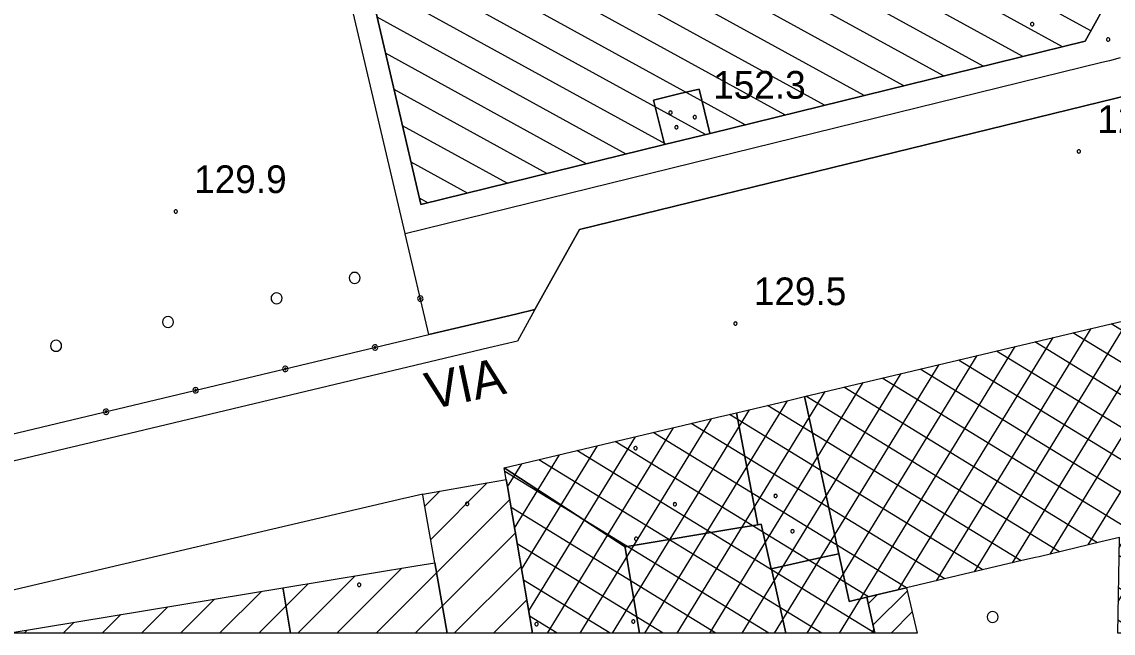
# Model space of a CAD drawing. Extents: x 513373 to 514978, y 5038576 to 5040180.
# Drawn here: x 513585.9 to 513645.1, y 5038580.1 to 5038613.3 of the extents above; entities that cross this region are included whole.
import ezdxf

# ---------------------------------------------------------------- set-up
doc = ezdxf.new("R2010")
doc.units = 0
for name, color, linetype in [('2010300', 7, 'Continuous'), ('B1211', 7, 'Continuous'), ('C1131', 7, 'Continuous'), ('C12211', 7, 'Continuous'), ('C1228', 7, 'Continuous'), ('C21195', 7, 'Continuous'), ('C2911', 7, 'Continuous'), ('CAMP_C12211', 7, 'Continuous'), ('CAMP_C1228', 7, 'Continuous'), ('CAMP_C21195', 7, 'Continuous'), ('Default', 7, 'Continuous'), ('F12107', 7, 'Continuous'), ('F12131', 7, 'Continuous'), ('F12132', 7, 'Continuous'), ('G4315', 7, 'Continuous'), ('TOP500', 7, 'Continuous'), ('TOP920', 7, 'Continuous')]:
    doc.layers.add(name, color=color, linetype=linetype)

# ---------------------------------------------------------------- blocks, each defined once
blk = doc.blocks.new('CAMP_E0F7581C')
at = {"layer": 'CAMP_C12211'}
for p, q in [((6.821, 3.003), (9.881, 6.062)), ((6.501, 4.804), (7.317, 5.62)), ((3.855, -2.085), (11.101, 5.161)), ((5.976, -2.085), (11.411, 3.35)), ((1.734, -2.085), (5.253, 1.434)), ((8.097, -2.085), (11.72, 1.538)), ((-2.509, -2.085), (0.173, 0.597)), ((-0.388, -2.085), (2.713, 1.016)), ((-4.63, -2.085), (-2.367, 0.178)), ((-6.752, -2.085), (-4.907, -0.24)), ((10.219, -2.085), (12.03, -0.273)), ((-10.994, -2.085), (-9.987, -1.078)), ((-8.873, -2.085), (-7.447, -0.659)), ((-13.116, -2.085), (-12.527, -1.496)), ((-15.237, -2.085), (-15.067, -1.915))]:
    blk.add_line(p, q, dxfattribs=at)
blk = doc.blocks.new('CAMP_A9D3BC00')
at = {"layer": 'CAMP_C1228'}
for p, q in [((7.809, -2.417), (16.196, 11.27)), ((5.746, -2.912), (14.137, 10.781)), ((9.499, -2.53), (17.768, 10.964)), ((20.694, 7.717), (15.259, 11.047)), ((3.699, -3.381), (12.079, 10.293)), ((20.631, 4.237), (11.12, 10.065)), ((20.663, 5.977), (13.189, 10.556)), ((1.642, -3.868), (10.02, 9.805)), ((20.599, 2.498), (9.05, 9.574)), ((9.443, -5.492), (18.939, 10.004)), ((-0.415, -4.354), (7.962, 9.316)), ((20.567, 0.758), (6.981, 9.083)), ((10.155, -7.201), (20.11, 9.044)), ((-5.679, -7.201), (3.845, 8.339)), ((-2.472, -4.84), (5.903, 8.828)), ((20.535, -0.982), (4.911, 8.592)), ((-7.438, -7.201), (1.786, 7.851)), ((20.503, -2.721), (2.842, 8.101)), ((-9.197, -7.201), (-0.272, 7.363)), ((20.439, -6.201), (-1.298, 7.119)), ((20.471, -4.461), (0.772, 7.61)), ((11.914, -7.201), (20.683, 7.109)), ((-10.956, -7.201), (-2.331, 6.874)), ((19.201, -7.202), (-3.367, 6.628)), ((-12.715, -7.201), (-4.389, 6.386)), ((8.321, -2.294), (-5.437, 6.137)), ((-16.234, -7.201), (-8.506, 5.409)), ((-14.475, -7.201), (-6.448, 5.898)), ((6.259, -2.789), (-7.506, 5.646)), ((-17.993, -7.201), (-10.565, 4.921)), ((4.172, -3.27), (-9.576, 5.155)), ((-19.752, -7.201), (-12.624, 4.432)), ((0.029, -4.249), (-13.715, 4.173)), ((2.101, -3.759), (-11.645, 4.664)), ((13.673, -7.201), (20.629, 4.15)), ((-21.512, -7.201), (-14.682, 3.944)), ((-2.043, -4.739), (-15.784, 3.682)), ((-22.918, -3.754), (-18.799, 2.967)), ((-22.534, -5.998), (-16.741, 3.455)), ((-4.114, -5.228), (-17.854, 3.191)), ((-23.301, -1.509), (-20.858, 2.479)), ((-3.77, -7.199), (-19.924, 2.7)), ((-23.685, 0.735), (-22.916, 1.99)), ((-6.637, -7.201), (-21.993, 2.209)), ((-9.508, -7.201), (-23.828, 1.575)), ((15.432, -7.202), (20.575, 1.19)), ((-12.379, -7.201), (-23.493, -0.39)), ((17.191, -7.202), (20.52, -1.769)), ((-15.249, -7.201), (-23.157, -2.355)), ((16.33, -7.202), (9.49, -3.01)), ((-18.12, -7.201), (-22.821, -4.321)), ((18.951, -7.202), (20.466, -4.729)), ((13.459, -7.201), (9.457, -4.749)), ((-20.991, -7.201), (-22.485, -6.286)), ((10.589, -7.201), (9.424, -6.488)), ((-3.919, -7.201), (-3.809, -7.021))]:
    blk.add_line(p, q, dxfattribs=at)
blk = doc.blocks.new('CAMP_71B7BAA1')
at = {"layer": 'CAMP_C12211'}
for p, q in [((9.95, 21.918), (9.723, 22.043)), ((10.549, 19.876), (7.693, 21.447)), ((11.149, 17.835), (5.663, 20.851)), ((11.748, 15.794), (3.634, 20.255)), ((12.348, 13.753), (1.605, 19.659)), ((12.947, 11.711), (-0.425, 19.063)), ((13.547, 9.67), (-0.607, 17.451)), ((14.146, 7.629), (-0.008, 15.41)), ((14.745, 5.587), (0.103, 13.637)), ((15.345, 3.546), (0.185, 11.881)), ((15.944, 1.505), (0.764, 9.85)), ((16.544, -0.536), (1.901, 7.514)), ((17.143, -2.578), (2.99, 5.203)), ((17.743, -4.619), (3.59, 3.162)), ((17.563, -6.232), (4.189, 1.121)), ((16.843, -7.548), (2.813, 0.165)), ((15.297, -8.41), (0.661, -0.364)), ((10.994, -9.468), (-4.284, -1.068)), ((13.146, -8.939), (-1.491, -0.892)), ((6.691, -10.525), (-9.252, -1.761)), ((8.843, -9.996), (-7.1, -1.232)), ((4.539, -11.054), (-10.74, -2.654)), ((2.388, -11.583), (-12.437, -3.433)), ((0.236, -12.112), (-14.4, -4.066)), ((-1.915, -12.641), (-16.551, -4.595)), ((-4.067, -13.17), (-18.703, -5.124)), ((-6.218, -13.699), (-20.854, -5.653)), ((-8.369, -14.228), (-21.878, -6.801)), ((-10.521, -14.757), (-21.418, -8.766)), ((-12.673, -15.286), (-20.957, -10.731)), ((-14.824, -15.814), (-20.496, -12.697)), ((-16.976, -16.343), (-20.035, -14.662)), ((-19.128, -16.872), (-19.574, -16.627))]:
    blk.add_line(p, q, dxfattribs=at)
blk = doc.blocks.new('CAMP_B5DA6E80')
at = {"layer": 'CAMP_C21195'}
for p, q in [((-1.083, 0.331), (-0.583, 0.831)), ((-0.829, -0.829), (1.037, 1.037)), ((0.155, -1.259), (1.303, -0.111))]:
    blk.add_line(p, q, dxfattribs=at)
blk = doc.blocks.new('03080200')
at = {"layer": 'Default'}
for p, q in [((-0.139, 0.046), (-0.146, 0)), ((-0.146, 0), (-0.139, -0.046)), ((-0.118, 0.086), (-0.139, 0.046)), ((-0.086, 0.118), (-0.118, 0.086)), ((-0.046, 0.139), (-0.086, 0.118)), ((0, 0.146), (-0.046, 0.139)), ((-0.042, 0.014), (-0.045, 0)), ((-0.045, 0), (-0.042, -0.014)), ((-0.036, 0.026), (-0.042, 0.014)), ((-0.026, 0.036), (-0.036, 0.026)), ((-0.014, 0.042), (-0.026, 0.036)), ((0, 0.045), (-0.014, 0.042)), ((0.046, 0.139), (0, 0.146)), ((0.014, 0.042), (0, 0.045)), ((0.026, 0.036), (0.014, 0.042)), ((0.036, 0.026), (0.026, 0.036)), ((0.042, 0.014), (0.036, 0.026)), ((0.045, 0), (0.042, 0.014)), ((0.042, -0.014), (0.045, 0)), ((0.086, 0.118), (0.046, 0.139)), ((0.118, 0.086), (0.086, 0.118)), ((0.139, 0.046), (0.118, 0.086)), ((0.146, 0), (0.139, 0.046)), ((0.139, -0.046), (0.146, 0)), ((-0.139, -0.046), (-0.118, -0.086)), ((-0.118, -0.086), (-0.086, -0.118)), ((-0.086, -0.118), (-0.046, -0.139)), ((-0.046, -0.139), (0, -0.146)), ((-0.042, -0.014), (-0.036, -0.026)), ((-0.036, -0.026), (-0.026, -0.036)), ((-0.026, -0.036), (-0.014, -0.042)), ((-0.014, -0.042), (0, -0.045)), ((0, -0.045), (0.014, -0.042)), ((0, -0.146), (0.046, -0.139)), ((0.014, -0.042), (0.026, -0.036)), ((0.026, -0.036), (0.036, -0.026)), ((0.036, -0.026), (0.042, -0.014)), ((0.046, -0.139), (0.086, -0.118)), ((0.086, -0.118), (0.118, -0.086)), ((0.118, -0.086), (0.139, -0.046))]:
    blk.add_line(p, q, dxfattribs=at)
blk = doc.blocks.new('08020400')
at = {"layer": 'Default'}
for p, q in [((-0.086, 0.028), (-0.09, 0)), ((-0.09, 0), (-0.086, -0.028)), ((-0.073, 0.053), (-0.086, 0.028)), ((-0.053, 0.073), (-0.073, 0.053)), ((-0.028, 0.086), (-0.053, 0.073)), ((0, 0.09), (-0.028, 0.086)), ((0.028, 0.086), (0, 0.09)), ((0.053, 0.073), (0.028, 0.086)), ((0.073, 0.053), (0.053, 0.073)), ((0.086, 0.028), (0.073, 0.053)), ((0.09, 0), (0.086, 0.028)), ((0.086, -0.028), (0.09, 0)), ((-0.086, -0.028), (-0.073, -0.053)), ((-0.073, -0.053), (-0.053, -0.073)), ((-0.053, -0.073), (-0.028, -0.086)), ((-0.028, -0.086), (0, -0.09)), ((0, -0.09), (0.028, -0.086)), ((0.028, -0.086), (0.053, -0.073)), ((0.053, -0.073), (0.073, -0.053)), ((0.073, -0.053), (0.086, -0.028))]:
    blk.add_line(p, q, dxfattribs=at)
blk = doc.blocks.new('NSIMB25')
at = {"layer": 'Default'}
for p, q in [((-0.086, 0.028), (-0.09, 0)), ((-0.09, 0), (-0.086, -0.028)), ((-0.073, 0.053), (-0.086, 0.028)), ((-0.053, 0.073), (-0.073, 0.053)), ((-0.028, 0.086), (-0.053, 0.073)), ((0, 0.09), (-0.028, 0.086)), ((0.028, 0.086), (0, 0.09)), ((0.053, 0.073), (0.028, 0.086)), ((0.073, 0.053), (0.053, 0.073)), ((0.086, 0.028), (0.073, 0.053)), ((0.09, 0), (0.086, 0.028)), ((0.086, -0.028), (0.09, 0)), ((-0.086, -0.028), (-0.073, -0.053)), ((-0.073, -0.053), (-0.053, -0.073)), ((-0.053, -0.073), (-0.028, -0.086)), ((-0.028, -0.086), (0, -0.09)), ((0, -0.09), (0.028, -0.086)), ((0.028, -0.086), (0.053, -0.073)), ((0.053, -0.073), (0.073, -0.053)), ((0.073, -0.053), (0.086, -0.028))]:
    blk.add_line(p, q, dxfattribs=at)
blk = doc.blocks.new('05010100')
at = {"layer": 'Default'}
for p, q in [((-0.143, 0.046), (-0.15, 0)), ((-0.15, 0), (-0.143, -0.046)), ((-0.121, 0.088), (-0.143, 0.046)), ((-0.088, 0.121), (-0.121, 0.088)), ((-0.046, 0.143), (-0.088, 0.121)), ((0, 0.15), (-0.046, 0.143)), ((0.046, 0.143), (0, 0.15)), ((0.088, 0.121), (0.046, 0.143)), ((0.121, 0.088), (0.088, 0.121)), ((0.143, 0.046), (0.121, 0.088)), ((0.15, 0), (0.143, 0.046)), ((0.143, -0.046), (0.15, 0)), ((-0.143, -0.046), (-0.121, -0.088)), ((-0.121, -0.088), (-0.088, -0.121)), ((-0.088, -0.121), (-0.046, -0.143)), ((-0.046, -0.143), (0, -0.15)), ((0, -0.15), (0.046, -0.143)), ((0.046, -0.143), (0.088, -0.121)), ((0.088, -0.121), (0.121, -0.088)), ((0.121, -0.088), (0.143, -0.046))]:
    blk.add_line(p, q, dxfattribs=at)
blk = doc.blocks.new('A$C3704598A')
at = {"layer": '2010300'}
for points in [[(234.926, -783.811), (239.656, -782.696), (240.683, -782.453), (243.098, -778.106), (275.603, -770.148), (276.632, -769.896), (275.194, -774.344), (275.191, -774.351), (276.759, -773.983), (277.346, -773.772), (279.141, -769.287), (276.899, -761.303), (276.167, -762.574), (274.781, -764.98), (274.477, -763.965), (273.197, -759.683), (268.828, -745.067), (271.049, -741.525), (270.763, -740.582), (268.839, -734.233), (267.364, -729.37)], [(234.601, -792.459), (233.662, -792.679), (233.579, -792.699), (226.471, -794.366), (202.43, -800.003)]]:
    blk.add_lwpolyline(points, dxfattribs=at)
at = {"layer": 'B1211'}
for points in [[(275.603, -770.148), (243.098, -778.106), (240.683, -782.453), (239.656, -782.696), (234.926, -783.811), (234.924, -783.805), (233.651, -778.34), (233.647, -778.325), (230.763, -766.025)], [(231.922, -765.74), (234.5, -776.734), (234.504, -776.749), (247.715, -773.503), (250.181, -772.896), (270.537, -767.892), (271.988, -765.243)]]:
    blk.add_lwpolyline(points, dxfattribs=at)
blk.add_lwpolyline([(239.733, -784.162), (238.193, -784.525), (218.713, -789.182), (196.51, -794.439), (195.488, -794.673), (173.196, -799.794), (172.259, -800.002), (165.65, -800.002), (186.154, -795.446), (186.667, -795.332), (187.178, -795.219), (234.926, -783.811), (239.656, -782.696), (240.683, -782.453)], close=True, dxfattribs=at)
at = {"layer": 'C1131'}
for points in [[(272.425, -768.805), (271.852, -768.961), (271.43, -769.053), (233.651, -778.34), (233.647, -778.325), (230.763, -766.025), (230.903, -765.991), (231.922, -765.74), (234.5, -776.734), (234.504, -776.749), (247.715, -773.503), (250.181, -772.896), (270.537, -767.892), (271.988, -765.243), (263.897, -737.693), (264.178, -737.61), (265.184, -737.315), (273.432, -765.399)], [(271.988, -765.243), (270.537, -767.892), (250.181, -772.896), (250.177, -772.88), (249.589, -770.491), (248.57, -770.741), (247.123, -771.097), (247.711, -773.486), (247.715, -773.503), (234.504, -776.749), (234.5, -776.734), (231.922, -765.74)]]:
    blk.add_lwpolyline(points, dxfattribs=at)
for points in [[(250.181, -772.896), (247.715, -773.503), (247.711, -773.486), (247.123, -771.097), (248.57, -770.741), (249.589, -770.491), (250.177, -772.88)], [(283.593, -784.25), (283.304, -800.004), (272.294, -800.004), (272.392, -794.811), (271.37, -795.057), (268.034, -795.858), (267.84, -795.893), (267.739, -795.911), (266.853, -796.12), (266.717, -796.152), (260.846, -797.54), (259.826, -797.781), (258.686, -798.051), (257.732, -798.292), (257.727, -798.27), (257.167, -795.702), (255.307, -787.173), (278.874, -781.582), (278.994, -781.553), (280.008, -781.312)], [(257.167, -795.702), (256.142, -795.927), (253.506, -796.508), (252.961, -794.089), (252.775, -794.12), (251.612, -788.05), (254.287, -787.415), (255.307, -787.173)], [(252.775, -794.12), (251.74, -794.291), (245.574, -795.315), (239.022, -791.036), (250.592, -788.292), (251.612, -788.05)], [(245.574, -795.315), (245.584, -795.378), (246.351, -800.004), (240.555, -800.003), (239.195, -792.051), (239.131, -791.677), (239.022, -791.036)], [(239.195, -792.051), (240.555, -800.003), (235.929, -800.003), (235.262, -796.188), (234.939, -794.366), (234.611, -792.516), (234.601, -792.459), (238.1, -791.855), (238.729, -791.747), (239.131, -791.677)], [(253.506, -796.508), (253.508, -796.516), (254.293, -800.004), (246.351, -800.004), (245.584, -795.378), (245.574, -795.315), (251.74, -794.291), (252.775, -794.12), (252.961, -794.089)], [(257.727, -798.27), (257.732, -798.292), (258.686, -798.051), (259.114, -800.004), (254.293, -800.004), (253.508, -796.516), (253.506, -796.508), (256.142, -795.927), (257.167, -795.702)], [(235.929, -800.003), (227.423, -800.003), (227.023, -797.613), (227.013, -797.548), (234.229, -796.359), (235.262, -796.188)], [(227.023, -797.613), (227.423, -800.003), (212.119, -800.003), (227.013, -797.548)], [(261.418, -800.004), (259.114, -800.004), (258.686, -798.051), (259.826, -797.781), (260.846, -797.54)]]:
    blk.add_lwpolyline(points, close=True, dxfattribs=at)
at = {"layer": 'C12211'}
blk.add_lwpolyline([(271.988, -765.243), (270.537, -767.892), (250.181, -772.896), (247.715, -773.503), (234.504, -776.749), (234.5, -776.734), (231.922, -765.74)], dxfattribs=at)
blk.add_lwpolyline([(239.195, -792.051), (240.555, -800.003), (212.119, -800.003), (227.013, -797.548), (234.229, -796.359), (235.262, -796.188), (234.939, -794.366), (234.611, -792.516), (234.601, -792.459), (238.1, -791.855), (238.729, -791.747), (239.131, -791.677)], close=True, dxfattribs=at)
at = {"layer": 'C1228'}
blk.add_lwpolyline([(272.392, -794.811), (271.37, -795.057), (268.034, -795.858), (267.84, -795.893), (267.739, -795.911), (266.853, -796.12), (266.717, -796.152), (260.846, -797.54), (259.826, -797.781), (258.686, -798.051), (259.114, -800.004), (240.555, -800.003), (239.195, -792.051), (239.131, -791.677), (239.022, -791.036), (250.592, -788.292), (251.612, -788.05), (254.287, -787.415), (255.307, -787.173), (278.874, -781.582)], dxfattribs=at)
at = {"layer": 'C21195'}
blk.add_lwpolyline([(261.418, -800.004), (259.114, -800.004), (258.686, -798.051), (259.826, -797.781), (260.846, -797.54)], close=True, dxfattribs=at)
at = {"layer": 'C2911'}
blk.add_lwpolyline([(182.854, -779.395), (182.893, -779.538), (186.751, -793.656), (187.176, -795.211), (187.178, -795.219), (234.926, -783.811), (234.924, -783.805), (233.651, -778.34)], dxfattribs=at)
for p, rotation in [((234.471, -781.859), 103.1178760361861), ((232.012, -784.507), 13.436390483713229), ((227.149, -785.669), 13.436390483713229), ((222.286, -786.831), 13.436390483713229), ((217.422, -787.993), 13.436390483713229)]:
    blk.add_blockref('03080200', p, dxfattribs=dict(at, rotation=rotation))
at = {"layer": 'CAMP_C12211'}
for name, p in [('CAMP_71B7BAA1', (253.999, -759.787)), ('CAMP_E0F7581C', (228.215, -797.918))]:
    blk.add_blockref(name, p, dxfattribs=at)
at = {"layer": 'CAMP_C1228'}
blk.add_blockref('CAMP_A9D3BC00', (262.883, -792.803), dxfattribs=at)
at = {"layer": 'CAMP_C21195'}
blk.add_blockref('CAMP_B5DA6E80', (259.849, -798.745), dxfattribs=at)
at = {"layer": 'F12107'}
for p in [(249.352, -772.013), (270.187, -773.873), (221.202, -777.132), (251.556, -783.213)]:
    blk.add_blockref('08020400', p, dxfattribs=at)
at = {"layer": 'F12131'}
for p in [(267.655, -766.973), (271.771, -767.807), (248.042, -771.771), (248.279, -793.014), (254.652, -794.477)]:
    blk.add_blockref('NSIMB25', p, dxfattribs=at)
at = {"layer": 'F12132'}
for p in [(248.357, -772.567), (246.144, -789.968), (253.739, -792.56), (237.013, -792.989), (246.174, -794.891), (231.153, -797.378), (240.773, -799.514), (246.022, -799.37)]:
    blk.add_blockref('NSIMB25', p, dxfattribs=at)
at = {"layer": 'G4315', "xscale": 2, "yscale": 2}
for p in [(230.906, -780.736), (226.674, -781.84), (220.786, -783.128), (214.714, -784.416), (265.509, -799.127)]:
    blk.add_blockref('05010100', p, dxfattribs=at)
at = {"layer": 'TOP500'}
blk.add_text('VIA', height=2, rotation=11.98374, dxfattribs=at).set_placement((234.99, -787.887))
at = {"layer": 'TOP920'}
for s, p in [('152.3', (250.352, -771.013)), ('129.6', (271.187, -772.873)), ('129.9', (222.202, -776.132)), ('129.5', (252.556, -782.213))]:
    blk.add_text(s, height=1.5, dxfattribs=at).set_placement(p)

msp = doc.modelspace()

# ---------------------------------------------------------------- block references
at = {"layer": 'Default'}
msp.add_blockref('A$C3704598A', (513373.046, 5039380.14), dxfattribs=at)

doc.saveas('drawing.dxf')
